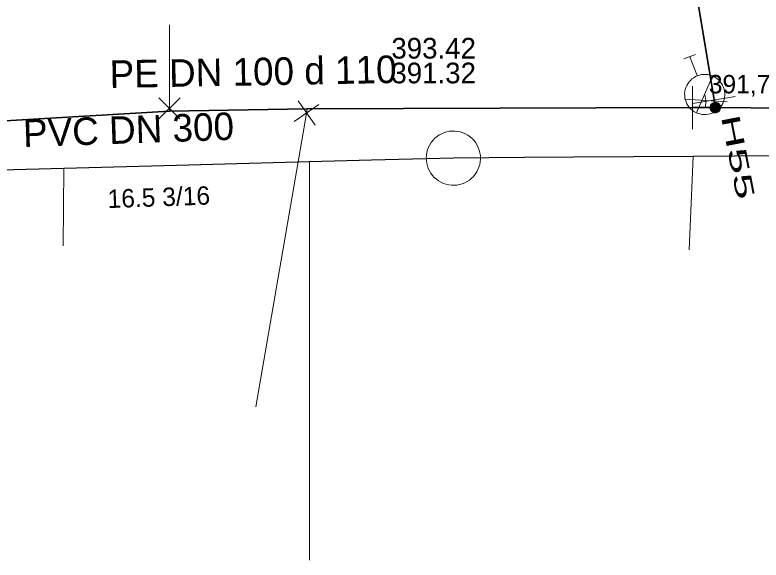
# Model space of a CAD drawing. Extents: x -772952 to -772403, y -1033777 to -1033210.
# Drawn here: x -772845.81 to -772813.34, y -1033330.65 to -1033306.93 of the extents above; entities that cross this region are included whole.
import ezdxf

# ---------------------------------------------------------------- set-up
doc = ezdxf.new("R2010")
doc.units = 0
doc.header["$LTSCALE"] = 0.36
for name, color, linetype, lineweight in [('15', 7, 'Continuous', 13), ('16', 7, 'Continuous', 35), ('2', 7, 'Continuous', 25), ('20', 7, 'Continuous', 13), ('4', 7, 'Continuous', 13), ('57', 7, 'Continuous', 13), ('59', 7, 'Continuous', 13)]:
    doc.layers.add(name, color=color, linetype=linetype, lineweight=lineweight)
for name, color, linetype in [('17', 7, 'Continuous'), ('3', 7, 'Continuous'), ('6', 7, 'Continuous')]:
    doc.layers.add(name, color=color, linetype=linetype)

msp = doc.modelspace()

# ---------------------------------------------------------------- linework, layer by layer
at = {"layer": '15'}
for p, q in [((-772816.315, -1033311.892), (-772816.32, -1033310.03)), ((-772838.628, -1033310.535), (-772839.551, -1033311.452)), ((-772838.635, -1033311.45), (-772839.543, -1033310.532)), ((-772833.491, -1033310.67), (-772832.752, -1033311.728)), ((-772816.667, -1033310.589), (-772814.809, -1033310.708)), ((-772814.465, -1033310.474), (-772816.303, -1033310.777)), ((-772833.653, -1033311.571), (-772832.588, -1033310.823))]:
    msp.add_line(p, q, dxfattribs=at)
for points in [[(-772815.291, -1033311.188), (-772815.241, -1033311.173), (-772815.195, -1033311.148), (-772815.156, -1033311.112), (-772815.125, -1033311.07), (-772815.106, -1033311.021), (-772815.097, -1033310.969), (-772815.102, -1033310.916), (-772815.117, -1033310.866), (-772815.144, -1033310.821), (-772815.18, -1033310.783), (-772815.224, -1033310.754), (-772815.273, -1033310.735), (-772815.326, -1033310.728), (-772815.377, -1033310.733), (-772815.427, -1033310.75), (-772815.473, -1033310.778), (-772815.51, -1033310.815), (-772815.537, -1033310.859), (-772815.555, -1033310.909), (-772815.561, -1033310.961), (-772815.554, -1033311.014), (-772815.536, -1033311.063), (-772815.507, -1033311.107), (-772815.47, -1033311.144), (-772815.424, -1033311.171), (-772815.375, -1033311.187), (-772815.322, -1033311.191)], [(-772815.296, -1033311.158), (-772815.249, -1033311.144), (-772815.206, -1033311.12), (-772815.171, -1033311.086), (-772815.146, -1033311.044), (-772815.131, -1033310.997), (-772815.128, -1033310.948), (-772815.136, -1033310.899), (-772815.157, -1033310.855), (-772815.187, -1033310.817), (-772815.226, -1033310.786), (-772815.271, -1033310.767), (-772815.32, -1033310.758), (-772815.369, -1033310.762), (-772815.415, -1033310.777), (-772815.456, -1033310.803), (-772815.491, -1033310.839), (-772815.515, -1033310.882), (-772815.528, -1033310.928), (-772815.53, -1033310.977), (-772815.52, -1033311.025), (-772815.497, -1033311.069), (-772815.466, -1033311.108), (-772815.427, -1033311.136), (-772815.381, -1033311.155), (-772815.332, -1033311.161)], [(-772815.301, -1033311.128), (-772815.258, -1033311.115), (-772815.219, -1033311.091), (-772815.189, -1033311.058), (-772815.168, -1033311.018), (-772815.158, -1033310.974), (-772815.161, -1033310.929), (-772815.174, -1033310.885), (-772815.199, -1033310.848), (-772815.233, -1033310.818), (-772815.274, -1033310.797), (-772815.318, -1033310.788), (-772815.363, -1033310.792), (-772815.406, -1033310.806), (-772815.443, -1033310.831), (-772815.472, -1033310.866), (-772815.492, -1033310.906), (-772815.501, -1033310.951), (-772815.496, -1033310.996), (-772815.481, -1033311.039), (-772815.455, -1033311.076), (-772815.421, -1033311.104), (-772815.379, -1033311.124), (-772815.334, -1033311.131)], [(-772815.306, -1033311.099), (-772815.266, -1033311.087), (-772815.233, -1033311.063), (-772815.207, -1033311.032), (-772815.192, -1033310.994), (-772815.187, -1033310.952), (-772815.196, -1033310.912), (-772815.215, -1033310.876), (-772815.244, -1033310.846), (-772815.28, -1033310.827), (-772815.32, -1033310.818), (-772815.361, -1033310.822), (-772815.399, -1033310.836), (-772815.431, -1033310.862), (-772815.455, -1033310.895), (-772815.468, -1033310.935), (-772815.469, -1033310.976), (-772815.459, -1033311.015), (-772815.438, -1033311.05), (-772815.407, -1033311.078), (-772815.37, -1033311.095), (-772815.329, -1033311.101)], [(-772815.311, -1033311.069), (-772815.276, -1033311.058), (-772815.248, -1033311.035), (-772815.227, -1033311.006), (-772815.218, -1033310.97), (-772815.221, -1033310.934), (-772815.234, -1033310.9), (-772815.259, -1033310.873), (-772815.291, -1033310.855), (-772815.326, -1033310.848), (-772815.363, -1033310.854), (-772815.395, -1033310.87), (-772815.421, -1033310.896), (-772815.436, -1033310.929), (-772815.441, -1033310.965), (-772815.433, -1033311.001), (-772815.413, -1033311.032), (-772815.386, -1033311.055), (-772815.352, -1033311.069), (-772815.316, -1033311.07)], [(-772815.316, -1033311.04), (-772815.286, -1033311.03), (-772815.263, -1033311.009), (-772815.251, -1033310.98), (-772815.249, -1033310.949), (-772815.258, -1033310.919), (-772815.279, -1033310.896), (-772815.305, -1033310.882), (-772815.337, -1033310.879), (-772815.366, -1033310.888), (-772815.391, -1033310.907), (-772815.406, -1033310.934), (-772815.41, -1033310.965), (-772815.402, -1033310.995), (-772815.384, -1033311.02), (-772815.357, -1033311.036), (-772815.327, -1033311.041)], [(-772815.321, -1033311.01), (-772815.298, -1033311.001), (-772815.283, -1033310.981), (-772815.278, -1033310.957), (-772815.285, -1033310.934), (-772815.302, -1033310.916), (-772815.325, -1033310.908), (-772815.35, -1033310.912), (-772815.369, -1033310.928), (-772815.379, -1033310.95), (-772815.378, -1033310.975), (-772815.366, -1033310.996), (-772815.345, -1033311.009)], [(-772815.326, -1033310.98), (-772815.312, -1033310.973), (-772815.308, -1033310.957), (-772815.314, -1033310.943), (-772815.329, -1033310.938), (-772815.344, -1033310.945), (-772815.35, -1033310.959), (-772815.345, -1033310.973), (-772815.331, -1033310.981)]]:
    msp.add_lwpolyline(points, close=True, dxfattribs=at)
at = {"layer": '16'}
for points in [[(-772830.179, -1033239.149), (-772828.5, -1033247.329), (-772824.879, -1033263.6), (-772822.929, -1033272.329), (-772821.21, -1033280.149), (-772817.589, -1033297.25), (-772817.462, -1033298.026), (-772815.385, -1033310.626), (-772815.329, -1033310.96), (-772812.21, -1033310.989), (-772811.827, -1033311.001)], [(-772816.318, -1033310.962), (-772833.089, -1033311.01), (-772839.089, -1033311.109), (-772848.469, -1033311.66), (-772849.008, -1033311.638)], [(-772815.329, -1033310.96), (-772815.76, -1033310.96), (-772816.318, -1033310.962)]]:
    msp.add_lwpolyline(points, dxfattribs=at)
at = {"layer": '2'}
for points in [[(-772776.31, -1033312.8), (-772777.043, -1033312.805), (-772777.699, -1033312.809), (-772779.326, -1033312.821), (-772784.589, -1033312.859), (-772788.311, -1033312.885), (-772790.991, -1033312.904), (-772802.376, -1033312.986), (-772810.876, -1033313.046), (-772816.3, -1033313.085), (-772821.487, -1033313.122), (-772823.628, -1033313.137), (-772826.73, -1033313.16)], [(-772826.73, -1033313.16), (-772830.297, -1033313.254), (-772832.988, -1033313.325), (-772838.783, -1033313.478), (-772843.679, -1033313.607), (-772847.513, -1033313.708), (-772852.1, -1033313.83)]]:
    msp.add_lwpolyline(points, dxfattribs=at)
at = {"layer": '20'}
for p, q in [((-772816.693, -1033308.844), (-772816.19, -1033308.646)), ((-772816.118, -1033309.568), (-772816.442, -1033308.745)), ((-772815.445, -1033309.59), (-772816.142, -1033311.194))]:
    msp.add_line(p, q, dxfattribs=at)
msp.add_lwpolyline([(-772814.975, -1033310.069), (-772815.012, -1033309.987), (-772815.058, -1033309.908), (-772815.113, -1033309.833), (-772815.174, -1033309.767), (-772815.243, -1033309.706), (-772815.318, -1033309.652), (-772815.398, -1033309.608), (-772815.481, -1033309.57), (-772815.569, -1033309.544), (-772815.658, -1033309.525), (-772815.75, -1033309.516), (-772815.842, -1033309.516), (-772815.933, -1033309.526), (-772816.022, -1033309.546), (-772816.109, -1033309.576), (-772816.193, -1033309.613), (-772816.271, -1033309.659), (-772816.345, -1033309.714), (-772816.412, -1033309.777), (-772816.473, -1033309.846), (-772816.525, -1033309.92), (-772816.572, -1033309.999), (-772816.607, -1033310.084), (-772816.636, -1033310.17), (-772816.654, -1033310.261), (-772816.663, -1033310.353), (-772816.662, -1033310.442), (-772816.651, -1033310.535), (-772816.631, -1033310.624), (-772816.603, -1033310.712), (-772816.565, -1033310.793), (-772816.519, -1033310.872), (-772816.463, -1033310.947), (-772816.403, -1033311.013), (-772816.334, -1033311.074), (-772816.259, -1033311.128), (-772816.179, -1033311.172), (-772816.095, -1033311.21), (-772816.008, -1033311.236), (-772815.919, -1033311.255), (-772815.827, -1033311.264), (-772815.735, -1033311.264), (-772815.645, -1033311.252), (-772815.555, -1033311.234), (-772815.468, -1033311.204), (-772815.384, -1033311.167), (-772815.306, -1033311.119), (-772815.232, -1033311.066), (-772815.164, -1033311.003), (-772815.104, -1033310.934), (-772815.051, -1033310.86), (-772815.005, -1033310.781), (-772814.969, -1033310.696), (-772814.941, -1033310.61), (-772814.923, -1033310.519), (-772814.914, -1033310.427), (-772814.915, -1033310.338), (-772814.925, -1033310.245), (-772814.945, -1033310.156), (-772814.975, -1033310.071)], dxfattribs=at)
at = {"layer": '4'}
msp.add_lwpolyline([(-772825.549, -1033313.16), (-772825.556, -1033313.041), (-772825.574, -1033312.924), (-772825.603, -1033312.808), (-772825.644, -1033312.697), (-772825.696, -1033312.59), (-772825.759, -1033312.489), (-772825.831, -1033312.394), (-772825.913, -1033312.308), (-772826.003, -1033312.23), (-772826.101, -1033312.161), (-772826.204, -1033312.103), (-772826.313, -1033312.056), (-772826.427, -1033312.019), (-772826.543, -1033311.994), (-772826.661, -1033311.982), (-772826.78, -1033311.981), (-772826.899, -1033311.992), (-772827.015, -1033312.015), (-772827.129, -1033312.049), (-772827.239, -1033312.095), (-772827.343, -1033312.152), (-772827.442, -1033312.219), (-772827.532, -1033312.295), (-772827.616, -1033312.38), (-772827.69, -1033312.474), (-772827.754, -1033312.574), (-772827.808, -1033312.68), (-772827.851, -1033312.791), (-772827.883, -1033312.905), (-772827.902, -1033313.023), (-772827.91, -1033313.142), (-772827.906, -1033313.26), (-772827.89, -1033313.378), (-772827.862, -1033313.494), (-772827.823, -1033313.606), (-772827.772, -1033313.714), (-772827.711, -1033313.816), (-772827.64, -1033313.912), (-772827.559, -1033313.999), (-772827.471, -1033314.079), (-772827.375, -1033314.149), (-772827.272, -1033314.209), (-772827.164, -1033314.258), (-772827.051, -1033314.296), (-772826.934, -1033314.322), (-772826.817, -1033314.337), (-772826.698, -1033314.34), (-772826.58, -1033314.331), (-772826.462, -1033314.31), (-772826.348, -1033314.277), (-772826.238, -1033314.233), (-772826.132, -1033314.178), (-772826.032, -1033314.112), (-772825.94, -1033314.037), (-772825.856, -1033313.953), (-772825.781, -1033313.861), (-772825.715, -1033313.762), (-772825.659, -1033313.657), (-772825.615, -1033313.547), (-772825.581, -1033313.433), (-772825.559, -1033313.316), (-772825.549, -1033313.197)], close=True, dxfattribs=at)
at = {"layer": '57'}
for p, q in [((-772816.3, -1033313.085), (-772816.47, -1033317.15)), ((-772843.679, -1033313.607), (-772843.72, -1033316.98)), ((-772832.988, -1033313.325), (-772832.99, -1033330.65))]:
    msp.add_line(p, q, dxfattribs=at)
at = {"layer": '59'}
for p, q in [((-772839.089, -1033311.109), (-772839.079, -1033307.359)), ((-772833.089, -1033311.01), (-772833.199, -1033311.64)), ((-772833.199, -1033311.64), (-772835.322, -1033323.98))]:
    msp.add_line(p, q, dxfattribs=at)
msp.add_lwpolyline([(-772815.76, -1033310.96), (-772815.739, -1033310.649), (-772815.789, -1033310.39)], dxfattribs=at)

# ---------------------------------------------------------------- texts
at = {"layer": '17'}
msp.add_text('PE DN 100 d 110 ', height=1.2, rotation=1, dxfattribs=at).set_placement((-772841.681, -1033310.106))
at = {"layer": '20'}
msp.add_text('391,79', height=0.8, dxfattribs=at).set_placement((-772815.612, -1033310.341))
at = {"layer": '20', "width": 1.9}
msp.add_text('H55 ', height=0.8, rotation=281, dxfattribs=at).set_placement((-772815.086, -1033311.351))
at = {"layer": '3'}
for s, height, p in [('PVC DN 300', 1.2, (-772845.439, -1033312.681)), ('16.5 3/16', 0.8, (-772841.766, -1033315.334))]:
    msp.add_text(s, height=height, rotation=2, dxfattribs=at).set_placement(p)
at = {"layer": '6'}
for s, p in [('393.42', (-772829.428, -1033308.827)), ('391.32', (-772829.428, -1033309.904))]:
    msp.add_text(s, height=0.9, dxfattribs=at).set_placement(p)

doc.saveas('drawing.dxf')
